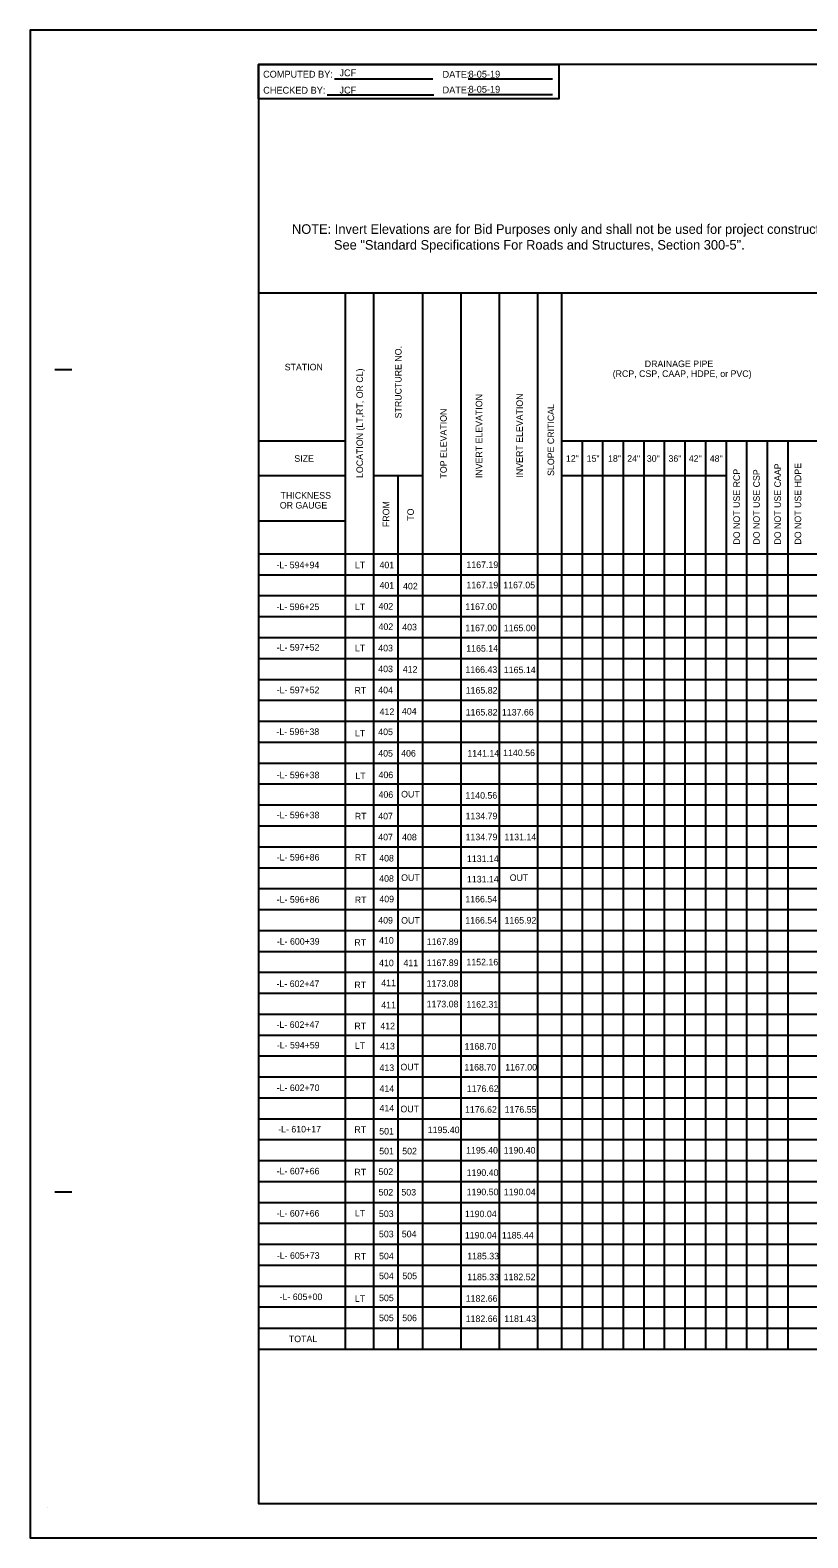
# Model space of a CAD drawing. Extents: x 809447 to 814738, y 647528 to 651206.
# Drawn here: x 809447 to 810014, y 650017 to 651117 of the extents above; entities that cross this region are included whole.
import ezdxf

# ---------------------------------------------------------------- set-up
doc = ezdxf.new("R2010")
doc.units = 0
doc.layers.add('Default', color=7, linetype='Continuous')

msp = doc.modelspace()

# ---------------------------------------------------------------- linework, layer by layer
at = {"layer": 'Default'}
for p, q in [((809669.2, 651081.5), (809740.8, 651081.5)), ((809766.6, 651081.4), (809828, 651081.4)), ((809663.8, 651069.8), (809741.5, 651069.8)), ((809766.7, 651069.9), (809828.1, 651069.9)), ((811113.6, 650925.1), (809613.6, 650925)), ((809677.2, 650154.3), (809677.2, 650925)), ((809697.7, 650154.3), (809697.7, 650925)), ((809733.5, 650154.3), (809733.5, 650925)), ((809761.5, 650154.3), (809761.4, 650925)), ((809789.4, 650154.3), (809789.4, 650925)), ((809817.4, 650154.3), (809817.4, 650925)), ((809834.9, 650154.3), (809834.9, 650925)), ((809465.1, 650869.4), (809477.6, 650869.4)), ((809677.2, 650817.1), (809613.6, 650817.1)), ((810352.4, 650817.2), (809834.9, 650817.1)), ((809849.9, 650154.3), (809849.9, 650817.1)), ((809864.9, 650154.3), (809864.9, 650817.1)), ((809879.9, 650154.3), (809879.9, 650817.1)), ((809894.9, 650154.3), (809894.9, 650817.1)), ((809909.9, 650154.3), (809909.9, 650817.1)), ((809924.9, 650154.3), (809924.9, 650817.1)), ((809939.9, 650154.3), (809939.9, 650817.1)), ((809954.9, 650154.3), (809954.9, 650817.1)), ((809969.9, 650154.3), (809969.9, 650817.1)), ((809984.9, 650154.3), (809984.9, 650817.1)), ((809999.9, 650154.3), (809999.9, 650817.1)), ((809677.2, 650791.7), (809613.6, 650791.7)), ((809733.5, 650791.7), (809697.7, 650791.7)), ((809715.6, 650154.3), (809715.6, 650791.7)), ((809954.9, 650791.8), (809834.9, 650791.7)), ((809677.2, 650758.6), (809613.6, 650758.6)), ((811113.6, 650734.7), (809613.6, 650734.7)), ((811113.6, 650719.4), (809613.6, 650719.4)), ((811113.6, 650704.1), (809613.6, 650704.1)), ((811113.6, 650688.9), (809613.6, 650688.9)), ((811113.6, 650673.6), (809613.6, 650673.6)), ((811113.6, 650658.3), (809613.6, 650658.3)), ((811113.6, 650643), (809613.6, 650643)), ((811113.6, 650627.8), (809613.6, 650627.8)), ((811113.6, 650612.5), (809613.6, 650612.5)), ((811113.6, 650597.3), (809613.6, 650597.3)), ((811113.6, 650582), (809613.6, 650582)), ((811113.6, 650566.7), (809613.6, 650566.7)), ((811113.6, 650551.5), (809613.6, 650551.5)), ((811113.6, 650536.2), (809613.6, 650536.2)), ((811113.6, 650520.9), (809613.6, 650520.9)), ((811113.6, 650505.6), (809613.6, 650505.6)), ((811113.6, 650490.4), (809613.6, 650490.4)), ((811113.6, 650475.1), (809613.6, 650475.1)), ((811113.6, 650459.8), (809613.6, 650459.8)), ((811113.6, 650444.5), (809613.6, 650444.5)), ((811113.6, 650429.3), (809613.6, 650429.3)), ((811113.6, 650414), (809613.6, 650414)), ((811113.6, 650398.8), (809613.6, 650398.8)), ((811113.6, 650383.5), (809613.6, 650383.5)), ((811113.6, 650368.3), (809613.6, 650368.3)), ((811113.6, 650353), (809613.6, 650353)), ((811113.6, 650337.8), (809613.6, 650337.8)), ((811113.6, 650322.5), (809613.6, 650322.5)), ((811113.6, 650307.2), (809613.6, 650307.2)), ((811113.6, 650291.9), (809613.6, 650291.9)), ((811113.6, 650276.7), (809613.6, 650276.7)), ((809465.1, 650269.4), (809477.6, 650269.4)), ((811113.6, 650261.4), (809613.6, 650261.4)), ((811113.6, 650246.2), (809613.6, 650246.2)), ((811113.6, 650230.9), (809613.6, 650230.9)), ((811113.6, 650215.7), (809613.6, 650215.7)), ((811113.6, 650200.4), (809613.6, 650200.4)), ((811113.6, 650185.2), (809613.6, 650185.2)), ((811113.6, 650169.6), (809613.6, 650169.6)), ((811113.6, 650154.3), (809613.6, 650154.3)), ((811113.6, 650154.3), (809613.6, 650154.3)), ((809460.1, 650039.4), (809460.1, 650039.4)), ((809613.6, 650041.9), (809613.6, 650041.9)), ((809613.6, 650041.9), (809613.6, 650041.9)), ((809613.6, 650041.9), (809613.6, 650041.9)), ((809613.6, 650041.9), (809613.6, 650041.9)), ((809613.6, 650041.9), (809613.6, 650041.9)), ((809613.6, 650041.9), (809613.6, 650041.9)), ((809613.6, 650041.9), (809613.6, 650041.9)), ((809613.6, 650041.9), (809613.6, 650041.9)), ((809613.6, 650041.9), (809613.6, 650041.9)), ((809447.1, 650016.9), (809447.1, 650016.9))]:
    msp.add_line(p, q, dxfattribs=at)
for points in [[(811131.1, 651116.9), (809447.1, 651116.9), (809447.1, 650016.9), (811131.1, 650016.9)], [(811113.6, 651091.9), (809613.6, 651091.9), (809613.6, 650041.9), (811113.6, 650041.9)], [(809613.6, 651091.9), (809832.6, 651091.9), (809832.6, 651066.9), (809613.6, 651066.9)]]:
    msp.add_lwpolyline(points, close=True, dxfattribs=at)

# ---------------------------------------------------------------- texts
for s, height, rotation, p in [('COMPUTED BY:', 5, 360, (809617, 651082.3)), ('JCF', 5, 360, (809672.7, 651083.3)), ('DATE:', 5, 360, (809747.9, 651082.2)), ('CHECKED BY:', 5, 360, (809617.1, 651070.6)), ('JCF', 5, 360, (809672.7, 651070.7)), ('DATE:', 5, 360, (809747.9, 651070.8)), ('STRUCTURE NO.', 4.8, 90, (809718, 650833.7)), ('STATION', 4.8, 360, (809632.8, 650868.7)), ('LOCATION (LT,RT, OR CL)', 4.8, 90, (809689.9, 650790.2)), ('INVERT ELEVATION', 4.8, 90, (809776.9, 650790.1)), ('INVERT ELEVATION', 4.8, 90, (809806.5, 650790.5)), ('TOP ELEVATION', 4.8, 90, (809751, 650789.8)), ('SLOPE CRITICAL', 4.8, 90, (809829.3, 650791.7)), ('DO NOT USE RCP', 4.8, 90, (809964.8, 650741.6)), ('DO NOT USE CSP', 4.8, 90, (809979.3, 650741.6)), ('DO NOT USE CAAP', 4.8, 90, (809994.7, 650741.6)), ('DO NOT USE HDPE', 4.8, 90, (810009.5, 650741.6)), ('FROM', 4.8, 90, (809709.1, 650754.4)), ('TO', 4.8, 90, (809727, 650759))]:
    msp.add_text(s, height=height, rotation=rotation, dxfattribs=at).set_placement(p)
for s, height, p in [('8-05-19', 5, (809766.9, 651082.3)), ('8-05-19', 5, (809766.9, 651071.3)), ('NOTE: Invert Elevations are for Bid Purposes only and shall not be used for project construction stakeout.', 7, (809638.1, 650968.3)), ('See "Standard Specifications For Roads and Structures, Section 300-5".', 7, (809668.7, 650956.8)), ('DRAINAGE PIPE', 4.8, (809895.4, 650871.1)), ('(RCP, CSP, CAAP, HDPE, or PVC)', 4.8, (809872, 650863.9)), ('SIZE', 4.8, (809639.8, 650802)), ('12"', 4.8, (809837.9, 650802)), ('15"', 4.8, (809853, 650802)), ('18"', 4.8, (809868.6, 650802)), ('24"', 4.8, (809882.6, 650802)), ('30"', 4.8, (809896.9, 650802)), ('36"', 4.8, (809912.7, 650802)), ('42"', 4.8, (809927.5, 650802)), ('48"', 4.8, (809942.8, 650802)), ('OR GAUGE', 4.8, (809629.2, 650767.9)), ('THICKNESS', 4.8, (809629.8, 650775.1)), ('-L- 594+94', 4.8, (809626.8, 650724.3)), ('LT', 4.8, (809684, 650724.3)), ('401', 4.8, (809701.9, 650724.3)), ('1167.19', 4.8, (809765.3, 650724.5)), ('401', 4.8, (809701.9, 650709.5)), ('402', 4.8, (809719.1, 650708.9)), ('1167.19', 4.8, (809765.3, 650709.7)), ('1167.05', 4.8, (809792.2, 650709.7)), ('-L- 596+25', 4.8, (809626.8, 650693.8)), ('LT', 4.8, (809684, 650693.8)), ('402', 4.8, (809701.2, 650694.2)), ('1167.00', 4.8, (809764.5, 650693.9)), ('402', 4.8, (809701.2, 650679.3)), ('403', 4.8, (809718.5, 650679)), ('1167.00', 4.8, (809764.5, 650678.4)), ('1165.00', 4.8, (809792.6, 650678.4)), ('-L- 597+52', 4.8, (809626.9, 650664.2)), ('LT', 4.8, (809684, 650663.8)), ('403', 4.8, (809701, 650663.7)), ('1165.14', 4.8, (809765.2, 650663.5)), ('403', 4.8, (809701, 650648.5)), ('412', 4.8, (809718.9, 650648.2)), ('1166.43', 4.8, (809764.6, 650648)), ('1165.14', 4.8, (809792.6, 650647.8)), ('-L- 597+52', 4.8, (809626.9, 650633.1)), ('RT', 4.8, (809683.7, 650632.9)), ('404', 4.8, (809701, 650633.1)), ('1165.82', 4.8, (809764.8, 650632.9)), ('412', 4.8, (809702, 650617.3)), ('404', 4.8, (809718.3, 650617.6)), ('1165.82', 4.8, (809764.8, 650616.9)), ('1137.66', 4.8, (809791.2, 650616.9)), ('-L- 596+38', 4.8, (809626.7, 650602.7)), ('LT', 4.8, (809684, 650601.6)), ('405', 4.8, (809701, 650602.6)), ('405', 4.8, (809701, 650586.9)), ('406', 4.8, (809717.7, 650586.9)), ('1141.14', 4.8, (809766, 650586.9)), ('1140.56', 4.8, (809792.1, 650587.3)), ('-L- 596+38', 4.8, (809626.9, 650571.1)), ('LT', 4.8, (809684.3, 650570.5)), ('406', 4.8, (809701.2, 650571.2)), ('406', 4.8, (809701.2, 650556.8)), ('OUT', 4.8, (809717.7, 650557.1)), ('1140.56', 4.8, (809764.6, 650556.2)), ('-L- 596+38', 4.8, (809626.9, 650541.9)), ('RT', 4.8, (809683.9, 650541.1)), ('407', 4.8, (809701, 650541.1)), ('1134.79', 4.8, (809764.7, 650541.2)), ('407', 4.8, (809701, 650525.8)), ('408', 4.8, (809718.4, 650525.8)), ('1134.79', 4.8, (809764.7, 650525.9)), ('1131.14', 4.8, (809793, 650525.9)), ('-L- 596+86', 4.8, (809626.9, 650511.1)), ('RT', 4.8, (809683.9, 650511)), ('408', 4.8, (809701.7, 650510.4)), ('1131.14', 4.8, (809765.7, 650510)), ('408', 4.8, (809701.7, 650495.6)), ('OUT', 4.8, (809717.7, 650496.2)), ('1131.14', 4.8, (809765.7, 650495.1)), ('OUT', 4.8, (809796.9, 650496.2)), ('-L- 596+86', 4.8, (809626.9, 650480.3)), ('409', 4.8, (809701.8, 650480.6)), ('1166.54', 4.8, (809764.5, 650480.5)), ('RT', 4.8, (809683.9, 650480)), ('409', 4.8, (809701, 650465.1)), ('OUT', 4.8, (809717.7, 650465)), ('1166.54', 4.8, (809764.5, 650465.1)), ('1165.92', 4.8, (809793.1, 650465.1)), ('-L- 600+39', 4.8, (809627, 650449.7)), ('RT', 4.8, (809683.6, 650448.9)), ('410', 4.8, (809701.6, 650450.4)), ('1167.89', 4.8, (809736.4, 650449.5)), ('410', 4.8, (809701.6, 650434)), ('411', 4.8, (809719.4, 650434)), ('1167.89', 4.8, (809736.4, 650434.1)), ('1152.16', 4.8, (809765.3, 650434.6)), ('-L- 602+47', 4.8, (809626.8, 650418.8)), ('RT', 4.8, (809683.6, 650418)), ('411', 4.8, (809703.2, 650419.4)), ('1173.08', 4.8, (809736.3, 650419)), ('411', 4.8, (809703.2, 650403.3)), ('1173.08', 4.8, (809736.3, 650404)), ('1162.31', 4.8, (809765.3, 650403.8)), ('-L- 602+47', 4.8, (809626.8, 650389)), ('RT', 4.8, (809683.6, 650388)), ('412', 4.8, (809702.5, 650388)), ('-L- 594+59', 4.8, (809627, 650374)), ('LT', 4.8, (809683.9, 650373.7)), ('413', 4.8, (809702.4, 650373.3)), ('1168.70', 4.8, (809764, 650373.1)), ('413', 4.8, (809701.9, 650357.5)), ('OUT', 4.8, (809717.2, 650358)), ('1168.70', 4.8, (809763.8, 650357.9)), ('1167.00', 4.8, (809793.6, 650357.9)), ('-L- 602+70', 4.8, (809626.9, 650342.9)), ('414', 4.8, (809701.9, 650342.3)), ('1176.62', 4.8, (809765.6, 650342.3)), ('414', 4.8, (809701.9, 650328)), ('OUT', 4.8, (809717.2, 650327.4)), ('1176.62', 4.8, (809764.3, 650327.1)), ('1176.55', 4.8, (809793.2, 650327.1)), ('-L- 610+17', 4.8, (809628, 650312.7)), ('RT', 4.8, (809683.6, 650312.4)), ('501', 4.8, (809701.7, 650311.2)), ('1195.40', 4.8, (809737.1, 650312.2)), ('501', 4.8, (809701.7, 650296.7)), ('502', 4.8, (809718.5, 650296.7)), ('1195.40', 4.8, (809765.1, 650297.3)), ('1190.40', 4.8, (809792.5, 650297.3)), ('-L- 607+66', 4.8, (809626.9, 650282.1)), ('RT', 4.8, (809683.6, 650281.4)), ('502', 4.8, (809701.2, 650281.7)), ('1190.40', 4.8, (809765.5, 650281)), ('502', 4.8, (809701.2, 650266.7)), ('503', 4.8, (809717.9, 650266.7)), ('1190.50', 4.8, (809765.5, 650266.9)), ('1190.04', 4.8, (809792.6, 650266.9)), ('-L- 607+66', 4.8, (809626.9, 650251.3)), ('LT', 4.8, (809683.9, 650251.4)), ('503', 4.8, (809701.5, 650251)), ('1190.04', 4.8, (809764.2, 650250.9)), ('503', 4.8, (809701.5, 650236.2)), ('504', 4.8, (809718.2, 650236.2)), ('1190.04', 4.8, (809764.2, 650235.3)), ('1185.44', 4.8, (809791.2, 650235.3)), ('-L- 605+73', 4.8, (809627, 650220.5)), ('RT', 4.8, (809683.6, 650219.9)), ('504', 4.8, (809701.6, 650220.1)), ('1185.33', 4.8, (809765.9, 650220.1)), ('504', 4.8, (809701.6, 650205.6)), ('505', 4.8, (809718.6, 650205.6)), ('1185.33', 4.8, (809765.9, 650204.9)), ('1182.52', 4.8, (809792.5, 650204.9)), ('-L- 605+00', 4.8, (809629, 650190.4)), ('LT', 4.8, (809683.9, 650189.1)), ('505', 4.8, (809701.6, 650189.6)), ('1182.66', 4.8, (809764.8, 650189.2)), ('505', 4.8, (809701.6, 650175)), ('506', 4.8, (809718.5, 650175)), ('1182.66', 4.8, (809764.8, 650174.4)), ('1181.43', 4.8, (809792.9, 650174.4)), ('TOTAL', 4.8, (809635.8, 650159.7))]:
    msp.add_text(s, height=height, dxfattribs=at).set_placement(p)

doc.saveas('drawing.dxf')
